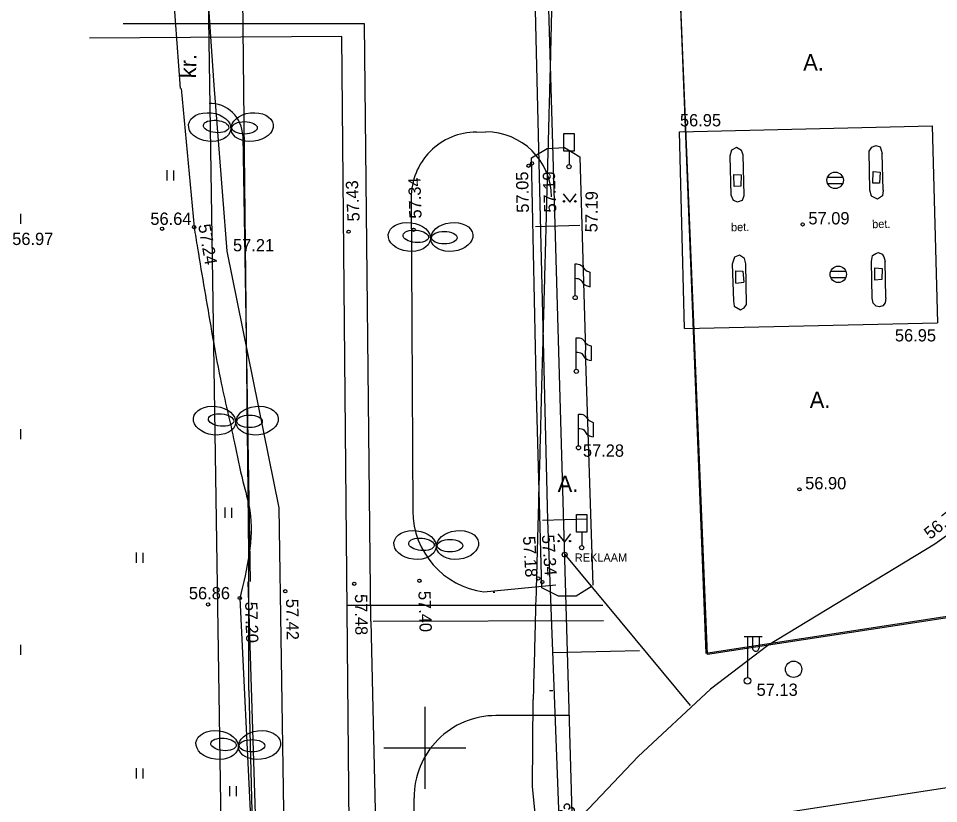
# Model space of a CAD drawing. Extents: x 9156 to 9809, y 2728 to 4000.
# Drawn here: x 9375.2 to 9431.4, y 3596.6 to 3644.5 of the extents above; entities that cross this region are included whole.
import ezdxf

# ---------------------------------------------------------------- set-up
doc = ezdxf.new("R2010")
doc.units = 0
for name, color, linetype in [('Level 11', 7, 'Continuous'), ('Level 12', 7, 'Continuous'), ('Level 14', 7, 'Continuous'), ('Level 15', 7, 'Continuous'), ('Level 16', 7, 'Continuous'), ('Level 18', 7, 'Continuous'), ('Level 54', 7, 'Continuous'), ('Level 56', 7, 'Continuous'), ('Level 7', 7, 'Continuous'), ('Level 8', 7, 'Continuous')]:
    doc.layers.add(name, color=color, linetype=linetype)

msp = doc.modelspace()

# ---------------------------------------------------------------- linework, layer by layer
at = {"layer": 'Level 11'}
for points in [[(9415.081, 3658.579), (9449.014, 3661.975), (9454.803, 3611.437), (9417.243, 3605.687)], [(9454.703, 3611.537), (9449.014, 3661.975), (9415.081, 3658.579), (9417.143, 3605.787)]]:
    msp.add_lwpolyline(points, close=True, dxfattribs=at)
at = {"layer": 'Level 12'}
for p, q in [((9389.26, 3611.821), (9388.899, 3645.893)), ((9389.26, 3603.506), (9389.26, 3611.821)), ((9389.26, 3603.506), (9390.852, 3539.152)), ((9407.609, 3603.506), (9407.816, 3603.506))]:
    msp.add_line(p, q, dxfattribs=at)
at = {"layer": 'Level 14'}
for p, q in [((9396.31, 3644.158), (9381.598, 3644.158)), ((9396.702, 3607.733), (9396.31, 3644.158)), ((9396.702, 3607.733), (9397.759, 3562.139)), ((9396.853, 3607.733), (9410.91, 3607.78))]:
    msp.add_line(p, q, dxfattribs=at)
at = {"layer": 'Level 15'}
msp.add_line((9407.788, 3605.822), (9413.097, 3605.937), dxfattribs=at)
at = {"layer": 'Level 16'}
for p, q in [((9394.939, 3643.387), (9379.538, 3643.283)), ((9395.524, 3581.023), (9394.939, 3643.387)), ((9395.222, 3608.716), (9410.87, 3608.706))]:
    msp.add_line(p, q, dxfattribs=at)
at = {"layer": 'Level 18'}
for p, q in [((9403.149, 3637.566), (9403.715, 3637.569)), ((9388.885, 3637.344), (9389.332, 3610.14)), ((9399.167, 3633.546), (9399.264, 3614.446)), ((9391.373, 3541.836), (9389.227, 3610.137)), ((9403.604, 3609.515), (9407.986, 3609.952)), ((9404.274, 3609.471), (9404.179, 3609.472)), ((9408.82, 3601.971), (9404.342, 3601.971)), ((9399.432, 3578.415), (9399.342, 3596.946))]:
    msp.add_line(p, q, dxfattribs=at)
for centre, radius, start, end in [((9386.885, 3637.312), 2, 0.9413, 91.579), ((9403.167, 3633.566), 4, 90.2544, 180.2913), ((9403.733, 3633.569), 4, 0.6132, 90.2544), ((9404.264, 3614.472), 5, 180.2913, 262.4109), ((9404.342, 3596.971), 5, 90, 180.2781)]:
    msp.add_arc(centre, radius, start, end, dxfattribs=at)
at = {"layer": 'Level 54'}
for p, q in [((9387.136, 3640.425), (9386.589, 3648.491)), ((9384.478, 3648.181), (9385.066, 3640.216)), ((9385.134, 3640.223), (9385.921, 3631.766)), ((9415.544, 3637.576), (9415.544, 3637.576)), ((9430.957, 3637.937), (9430.957, 3637.937)), ((9407.459, 3636.565), (9407.459, 3636.565)), ((9408.531, 3636.632), (9408.531, 3636.632)), ((9418.704, 3636.46), (9418.704, 3636.46)), ((9419.026, 3636.614), (9419.026, 3636.614)), ((9419.328, 3636.436), (9419.328, 3636.436)), ((9427.276, 3636.639), (9427.276, 3636.639)), ((9427.526, 3636.748), (9427.526, 3636.748)), ((9427.783, 3636.657), (9427.783, 3636.657)), ((9406.5, 3635.984), (9406.5, 3635.984)), ((9408.798, 3636.407), (9408.798, 3635.582)), ((9409.457, 3636.062), (9409.457, 3636.062)), ((9418.608, 3636.099), (9418.608, 3636.099)), ((9419.425, 3636.182), (9419.425, 3636.182)), ((9427.117, 3636.399), (9427.117, 3636.399)), ((9427.915, 3636.262), (9427.915, 3636.262)), ((9406.326, 3635.505), (9406.326, 3635.505)), ((9406.54, 3635.649), (9406.54, 3635.649)), ((9408.798, 3635.456), (9408.798, 3635.456)), ((9384.264, 3635.232), (9384.264, 3634.612)), ((9384.669, 3635.22), (9384.669, 3634.612)), ((9418.862, 3634.976), (9418.862, 3634.976)), ((9419.3, 3634.949), (9419.3, 3634.949)), ((9424.58, 3634.821), (9425.496, 3634.821)), ((9427.352, 3635.161), (9427.352, 3635.161)), ((9427.783, 3635.11), (9427.783, 3635.11)), ((9418.867, 3634.236), (9418.867, 3634.236)), ((9419.286, 3634.267), (9419.286, 3634.267)), ((9424.58, 3634.421), (9425.496, 3634.421)), ((9425.038, 3634.621), (9425.038, 3634.621)), ((9427.334, 3634.439), (9427.334, 3634.439)), ((9427.747, 3634.438), (9427.747, 3634.438)), ((9408.436, 3633.787), (9408.839, 3633.282)), ((9408.839, 3633.282), (9409.236, 3633.787)), ((9418.68, 3633.736), (9418.68, 3633.736)), ((9419.479, 3633.686), (9419.479, 3633.686)), ((9427.158, 3634.01), (9427.158, 3634.01)), ((9427.255, 3633.66), (9427.255, 3633.66)), ((9427.927, 3633.673), (9427.927, 3633.673)), ((9427.977, 3634.023), (9427.977, 3634.023)), ((9418.808, 3633.409), (9418.808, 3633.409)), ((9419.083, 3633.311), (9419.083, 3633.311)), ((9419.388, 3633.412), (9419.388, 3633.412)), ((9427.623, 3633.47), (9427.623, 3633.47)), ((9375.322, 3632.584), (9375.322, 3631.975)), ((9423.056, 3631.931), (9423.056, 3631.931)), ((9383.969, 3631.668), (9383.969, 3631.668)), ((9385.921, 3631.766), (9385.921, 3631.766)), ((9395.346, 3631.488), (9395.346, 3631.488)), ((9399.316, 3631.606), (9399.316, 3631.606)), ((9406.75, 3631.786), (9406.75, 3631.786)), ((9409.452, 3631.868), (9409.452, 3631.868)), ((9387.944, 3630.289), (9387.944, 3630.289)), ((9418.891, 3629.932), (9418.891, 3629.932)), ((9419.192, 3630.05), (9419.192, 3630.05)), ((9419.498, 3629.849), (9419.498, 3629.849)), ((9427.322, 3630.029), (9427.322, 3630.029)), ((9427.518, 3630.165), (9427.518, 3630.165)), ((9427.676, 3630.212), (9427.676, 3630.212)), ((9427.901, 3630.126), (9427.901, 3630.126)), ((9428.018, 3629.963), (9428.018, 3629.963)), ((9409.177, 3627.593), (9409.177, 3629.519)), ((9418.763, 3629.51), (9418.763, 3629.51)), ((9419.591, 3629.531), (9419.591, 3629.531)), ((9427.253, 3629.669), (9427.253, 3629.669)), ((9427.464, 3629.281), (9427.464, 3629.281)), ((9427.917, 3629.241), (9427.917, 3629.241)), ((9428.084, 3629.675), (9428.084, 3629.675)), ((9410.078, 3629.015), (9410.078, 3628.125)), ((9418.978, 3629.104), (9418.978, 3629.104)), ((9419.415, 3629.076), (9419.415, 3629.076)), ((9424.772, 3629.086), (9425.688, 3629.086)), ((9424.772, 3628.686), (9425.688, 3628.686)), ((9425.23, 3628.886), (9425.23, 3628.886)), ((9427.895, 3628.563), (9427.895, 3628.563)), ((9418.972, 3628.348), (9418.972, 3628.348)), ((9419.473, 3628.402), (9419.473, 3628.402)), ((9427.46, 3628.539), (9427.46, 3628.539)), ((9409.177, 3627.467), (9409.177, 3627.467)), ((9427.295, 3627.44), (9427.295, 3627.44)), ((9428.123, 3627.448), (9428.123, 3627.448)), ((9418.83, 3627.27), (9418.83, 3627.27)), ((9418.886, 3626.952), (9418.886, 3626.952)), ((9419.632, 3627.037), (9419.632, 3627.037)), ((9427.357, 3627.124), (9427.357, 3627.124)), ((9427.544, 3626.949), (9427.544, 3626.949)), ((9427.748, 3626.912), (9427.748, 3626.912)), ((9427.941, 3626.957), (9427.941, 3626.957)), ((9428.087, 3627.148), (9428.087, 3627.148)), ((9419.253, 3626.727), (9419.253, 3626.727)), ((9419.495, 3626.849), (9419.495, 3626.849)), ((9431.278, 3625.922), (9431.278, 3625.922)), ((9415.855, 3625.589), (9415.855, 3625.589)), ((9409.245, 3623.093), (9409.245, 3625.019)), ((9409.811, 3624.243), (9409.811, 3624.243)), ((9410.146, 3624.515), (9410.146, 3623.625)), ((9409.245, 3622.967), (9409.245, 3622.967)), ((9406.818, 3621.548), (9406.818, 3621.548)), ((9409.376, 3618.432), (9409.376, 3620.358)), ((9410.277, 3619.854), (9410.277, 3618.964)), ((9375.322, 3619.433), (9375.322, 3618.824)), ((9409.376, 3618.306), (9409.376, 3618.306)), ((9422.858, 3615.771), (9422.858, 3615.771)), ((9387.794, 3614.656), (9387.794, 3614.036)), ((9388.199, 3614.645), (9388.199, 3614.036)), ((9391.116, 3614.638), (9391.116, 3614.638)), ((9407.173, 3613.877), (9407.173, 3613.877)), ((9407.476, 3613.881), (9407.476, 3613.881)), ((9409.914, 3613.957), (9409.914, 3613.957)), ((9408.115, 3613.062), (9408.518, 3612.557)), ((9408.518, 3612.557), (9408.915, 3613.062)), ((9409.574, 3613.162), (9409.574, 3612.337)), ((9431.117, 3612.429), (9431.117, 3612.429)), ((9382.392, 3611.913), (9382.392, 3611.293)), ((9382.798, 3611.902), (9382.798, 3611.293)), ((9408.535, 3611.789), (9408.535, 3611.789)), ((9409.574, 3612.211), (9409.574, 3612.211)), ((9399.669, 3610.192), (9399.669, 3610.192)), ((9406.917, 3610.334), (9406.917, 3610.334)), ((9407.171, 3610.117), (9407.171, 3610.117)), ((9391.483, 3609.557), (9391.483, 3609.557)), ((9395.696, 3610.009), (9395.696, 3610.009)), ((9407.132, 3609.759), (9407.132, 3609.759)), ((9410.204, 3609.858), (9410.204, 3609.858)), ((9388.707, 3609.142), (9388.707, 3609.142)), ((9388.707, 3609.142), (9389.518, 3592.556)), ((9408.147, 3609.25), (9408.147, 3609.25)), ((9409.232, 3609.263), (9409.232, 3609.263)), ((9386.777, 3608.752), (9386.777, 3608.752)), ((9419.492, 3606.796), (9420.592, 3606.796)), ((9419.692, 3606.796), (9419.692, 3604.296)), ((9419.992, 3606.796), (9419.992, 3606.096)), ((9420.392, 3606.796), (9420.392, 3606.096)), ((9375.322, 3606.282), (9375.322, 3605.673)), ((9420.928, 3606.248), (9420.928, 3606.248)), ((9419.692, 3604.096), (9419.692, 3604.096)), ((9417.439, 3603.592), (9417.439, 3603.592)), ((9400, 3602.5), (9400, 3597.5)), ((9400, 3602.5), (9400, 3597.5)), ((9400, 3602.5), (9400, 3597.5)), ((9416.186, 3602.596), (9416.186, 3602.596)), ((9397.5, 3600), (9402.5, 3600)), ((9397.5, 3600), (9402.5, 3600)), ((9397.5, 3600), (9402.5, 3600)), ((9413.009, 3599.472), (9413.009, 3599.472)), ((9382.392, 3598.762), (9382.392, 3598.142)), ((9382.798, 3598.75), (9382.798, 3598.142)), ((9388.073, 3597.67), (9388.073, 3597.05)), ((9388.478, 3597.659), (9388.478, 3597.05))]:
    msp.add_line(p, q, dxfattribs=at)
for points in [[(9406.651, 3648.489), (9406.796, 3642.411)], [(9406.796, 3642.411), (9407.476, 3613.881), (9408.676, 3582.388), (9410.387, 3515.117)], [(9438.722, 3642.411), (9439.009, 3638.117), (9439.783, 3627.178), (9439.69, 3625.163), (9439.116, 3623.225), (9438.356, 3621.375), (9436.997, 3618.72), (9435.277, 3616.16), (9432.91, 3613.707), (9431.117, 3612.429), (9420.928, 3606.248), (9417.439, 3603.592), (9413.009, 3599.472), (9408.878, 3595.102), (9406.951, 3592.745)], [(9397.129, 3380.652), (9395.019, 3412.343), (9393.756, 3460.883), (9392.807, 3509.978), (9391.971, 3559.264), (9391.116, 3614.638), (9387.944, 3630.289), (9387.153, 3640.427)], [(9415.855, 3625.589), (9415.544, 3637.576), (9430.957, 3637.937), (9431.278, 3625.922)], [(9410.204, 3609.858), (9409.232, 3609.263), (9408.147, 3609.25), (9407.132, 3609.759), (9406.818, 3621.548), (9406.5, 3635.984), (9407.459, 3636.565), (9408.531, 3636.632), (9409.457, 3636.062), (9409.811, 3624.243)], [(9419.425, 3636.182), (9419.328, 3636.436), (9419.026, 3636.614), (9418.704, 3636.46), (9418.608, 3636.099), (9418.68, 3633.736), (9418.808, 3633.409), (9419.083, 3633.311), (9419.388, 3633.412), (9419.479, 3633.686)], [(9427.977, 3634.023), (9427.927, 3633.673), (9427.623, 3633.47), (9427.255, 3633.66), (9427.158, 3634.01), (9427.117, 3636.399), (9427.276, 3636.639), (9427.526, 3636.748), (9427.783, 3636.657), (9427.915, 3636.262)], [(9419.479, 3633.686), (9419.425, 3636.182)], [(9427.977, 3634.023), (9427.915, 3636.262)], [(9419.286, 3634.267), (9418.867, 3634.236), (9418.862, 3634.976), (9419.3, 3634.949)], [(9419.3, 3634.949), (9419.286, 3634.267)], [(9427.783, 3635.11), (9427.747, 3634.438), (9427.334, 3634.439), (9427.352, 3635.161)], [(9427.352, 3635.161), (9427.783, 3635.11)], [(9409.452, 3631.868), (9406.75, 3631.786)], [(9419.591, 3629.531), (9419.498, 3629.849), (9419.192, 3630.05), (9418.891, 3629.932), (9418.763, 3629.51), (9418.83, 3627.27), (9418.886, 3626.952), (9419.253, 3626.727), (9419.495, 3626.849), (9419.632, 3627.037)], [(9428.123, 3627.448), (9428.087, 3627.148), (9427.941, 3626.957), (9427.748, 3626.912), (9427.544, 3626.949), (9427.357, 3627.124), (9427.295, 3627.44), (9427.253, 3629.669), (9427.322, 3630.029), (9427.518, 3630.165), (9427.676, 3630.212), (9427.901, 3630.126), (9428.018, 3629.963), (9428.084, 3629.675)], [(9419.632, 3627.037), (9419.591, 3629.531)], [(9427.917, 3629.241), (9427.895, 3628.563), (9427.46, 3628.539), (9427.464, 3629.281)], [(9427.464, 3629.281), (9427.917, 3629.241)], [(9428.123, 3627.448), (9428.084, 3629.675)], [(9418.972, 3628.348), (9418.978, 3629.104), (9419.415, 3629.076), (9419.473, 3628.402)], [(9418.972, 3628.348), (9419.473, 3628.402)], [(9415.855, 3625.589), (9431.278, 3625.922)], [(9410.275, 3609.929), (9409.811, 3624.243)], [(9409.914, 3613.957), (9407.173, 3613.877)], [(9408.535, 3611.789), (9416.186, 3602.596)], [(9409.112, 3500.044), (9408.382, 3542.315), (9408.497, 3570.133), (9408.227, 3581.28), (9406.571, 3597.619), (9406.61, 3602.955)]]:
    msp.add_lwpolyline(points, dxfattribs=at)
for points in [[(9408.481, 3637.483), (9409.115, 3637.483), (9409.115, 3636.407), (9408.481, 3636.407)], [(9409.257, 3614.238), (9409.891, 3614.238), (9409.891, 3613.162), (9409.257, 3613.162)]]:
    msp.add_lwpolyline(points, close=True, dxfattribs=at)
for centre, radius in [((9406.326, 3635.505), 0.1), ((9406.54, 3635.649), 0.1), ((9408.798, 3635.456), 0.126), ((9425.038, 3634.621), 0.5), ((9408.486, 3633.337), 0.0428), ((9409.186, 3633.337), 0.0452), ((9423.056, 3631.931), 0.1), ((9383.969, 3631.668), 0.1), ((9385.921, 3631.766), 0.1), ((9395.346, 3631.488), 0.1), ((9399.316, 3631.606), 0.1), ((9425.23, 3628.886), 0.5), ((9409.177, 3627.467), 0.126), ((9409.245, 3622.967), 0.126), ((9409.376, 3618.306), 0.126), ((9422.858, 3615.771), 0.1), ((9408.165, 3612.612), 0.0428), ((9408.865, 3612.612), 0.0452), ((9409.574, 3612.211), 0.126), ((9408.535, 3611.789), 0.148), ((9395.696, 3610.009), 0.1), ((9399.669, 3610.192), 0.1), ((9406.917, 3610.334), 0.1), ((9407.171, 3610.117), 0.1), ((9391.483, 3609.557), 0.1), ((9388.707, 3609.142), 0.1), ((9386.777, 3608.752), 0.1), ((9422.503, 3604.794), 0.5), ((9419.692, 3604.096), 0.2)]:
    msp.add_circle(centre, radius, dxfattribs=at)
msp.add_arc((9420.192, 3606.096), 0.2, 179.9393, 0.0607, dxfattribs=at)
for points, degree in [([(9436.731, 3685.954), (9412.763, 3679.921), (9412.256, 3679.783), (9412.019, 3679.731), (9411.816, 3679.574), (9411.512, 3678.968), (9408.609, 3671.162), (9408.49, 3670.833), (9408.444, 3670.642), (9408.427, 3670.482), (9407.671, 3642.411)], 3), ([(9407.671, 3642.411), (9407.414, 3632.864), (9407.07, 3620.079), (9406.61, 3602.955)], 2)]:
    msp.add_open_spline(points, degree=degree, dxfattribs=at)
for points in [[(9385.921, 3631.766), (9386.128, 3630.481), (9386.99, 3625.4), (9387.525, 3622.489), (9388.384, 3618.613), (9388.897, 3616.251), (9389.316, 3614.486), (9388.707, 3609.142)], [(9409.177, 3629.519), (9409.527, 3629.454), (9409.759, 3629.188), (9410.078, 3629.015)], [(9409.177, 3628.644), (9409.504, 3628.555), (9409.671, 3628.322), (9410.079, 3628.126)], [(9409.245, 3625.019), (9409.595, 3624.954), (9409.827, 3624.688), (9410.146, 3624.515)], [(9409.245, 3624.144), (9409.572, 3624.055), (9409.739, 3623.822), (9410.147, 3623.626)], [(9409.376, 3620.358), (9409.726, 3620.293), (9409.958, 3620.027), (9410.277, 3619.854)], [(9409.376, 3619.483), (9409.703, 3619.394), (9409.87, 3619.161), (9410.278, 3618.965)]]:
    msp.add_spline(points, degree=3, dxfattribs=at)
at = {"layer": 'Level 56'}
for p, q in [((9403.149, 3637.566), (9403.715, 3637.569)), ((9388.885, 3637.344), (9389.332, 3610.14)), ((9399.167, 3633.546), (9399.264, 3614.446)), ((9391.373, 3541.836), (9389.227, 3610.137)), ((9403.604, 3609.515), (9407.986, 3609.952)), ((9404.274, 3609.471), (9404.179, 3609.472)), ((9408.82, 3601.971), (9404.342, 3601.971)), ((9399.432, 3578.415), (9399.342, 3596.946))]:
    msp.add_line(p, q, dxfattribs=at)
for centre, radius, start, end in [((9386.885, 3637.312), 2, 0.9413, 91.579), ((9403.167, 3633.566), 4, 90.2544, 180.2913), ((9403.733, 3633.569), 4, 0.6132, 90.2544), ((9404.264, 3614.472), 5, 180.2913, 262.4109), ((9404.342, 3596.971), 5, 90, 180.2781)]:
    msp.add_arc(centre, radius, start, end, dxfattribs=at)
at = {"layer": 'Level 7'}
for p, q in [((9387.795, 3580.728), (9386.2, 3684.47)), ((9407.89, 3634.03), (9406.73, 3674)), ((9409.05, 3594.06), (9407.89, 3634.03)), ((9435.465, 3598.13), (9409.05, 3594.06))]:
    msp.add_line(p, q, dxfattribs=at)
at = {"layer": 'Level 8'}
for centre, major_axis, ratio in [((9386.868, 3637.867), (1.285, -0.15), 0.674652), ((9386.868, 3637.867), (1.285, -0.15), 0.674652), ((9386.868, 3637.867), (1.285, -0.15), 0.674652), ((9386.868, 3637.867), (1.285, -0.15), 0.674652), ((9389.46, 3637.867), (-1.285, -0.15), 0.674652), ((9389.46, 3637.867), (-1.285, -0.15), 0.674652), ((9389.46, 3637.867), (-1.285, -0.15), 0.674652), ((9389.46, 3637.867), (-1.285, -0.15), 0.674652), ((9387.263, 3637.904), (0.774, -0.072), 0.486914), ((9387.263, 3637.904), (0.774, -0.072), 0.486914), ((9387.263, 3637.904), (0.774, -0.072), 0.486914), ((9387.263, 3637.904), (0.774, -0.072), 0.486914), ((9389, 3637.824), (-0.778, 0.002), 0.486914), ((9389, 3637.824), (-0.778, 0.002), 0.486914), ((9389, 3637.824), (-0.778, 0.002), 0.486914), ((9389, 3637.824), (-0.778, 0.002), 0.486914), ((9399.054, 3631.165), (1.285, -0.15), 0.674652), ((9399.054, 3631.165), (1.285, -0.15), 0.674652), ((9399.054, 3631.165), (1.285, -0.15), 0.674652), ((9399.054, 3631.165), (1.285, -0.15), 0.674652), ((9401.646, 3631.165), (-1.285, -0.15), 0.674652), ((9401.646, 3631.165), (-1.285, -0.15), 0.674652), ((9401.646, 3631.165), (-1.285, -0.15), 0.674652), ((9401.646, 3631.165), (-1.285, -0.15), 0.674652), ((9399.449, 3631.202), (0.774, -0.072), 0.486914), ((9399.449, 3631.202), (0.774, -0.072), 0.486914), ((9399.449, 3631.202), (0.774, -0.072), 0.486914), ((9399.449, 3631.202), (0.774, -0.072), 0.486914), ((9401.186, 3631.122), (-0.778, 0.002), 0.486914), ((9401.186, 3631.122), (-0.778, 0.002), 0.486914), ((9401.186, 3631.122), (-0.778, 0.002), 0.486914), ((9401.186, 3631.122), (-0.778, 0.002), 0.486914), ((9387.17, 3619.965), (1.285, -0.15), 0.674652), ((9387.17, 3619.965), (1.285, -0.15), 0.674652), ((9387.17, 3619.965), (1.285, -0.15), 0.674652), ((9387.17, 3619.965), (1.285, -0.15), 0.674652), ((9389.762, 3619.965), (-1.285, -0.15), 0.674652), ((9389.762, 3619.965), (-1.285, -0.15), 0.674652), ((9389.762, 3619.965), (-1.285, -0.15), 0.674652), ((9389.762, 3619.965), (-1.285, -0.15), 0.674652), ((9387.565, 3620.001), (0.774, -0.072), 0.486914), ((9387.565, 3620.001), (0.774, -0.072), 0.486914), ((9387.565, 3620.001), (0.774, -0.072), 0.486914), ((9387.565, 3620.001), (0.774, -0.072), 0.486914), ((9389.302, 3619.921), (-0.778, 0.002), 0.486914), ((9389.302, 3619.921), (-0.778, 0.002), 0.486914), ((9389.302, 3619.921), (-0.778, 0.002), 0.486914), ((9389.302, 3619.921), (-0.778, 0.002), 0.486914), ((9399.402, 3612.378), (1.285, -0.15), 0.674652), ((9399.402, 3612.378), (1.285, -0.15), 0.674652), ((9399.402, 3612.378), (1.285, -0.15), 0.674652), ((9399.402, 3612.378), (1.285, -0.15), 0.674652), ((9401.995, 3612.378), (-1.285, -0.15), 0.674652), ((9401.995, 3612.378), (-1.285, -0.15), 0.674652), ((9401.995, 3612.378), (-1.285, -0.15), 0.674652), ((9401.995, 3612.378), (-1.285, -0.15), 0.674652), ((9399.797, 3612.414), (0.774, -0.072), 0.486914), ((9399.797, 3612.414), (0.774, -0.072), 0.486914), ((9399.797, 3612.414), (0.774, -0.072), 0.486914), ((9399.797, 3612.414), (0.774, -0.072), 0.486914), ((9401.535, 3612.334), (-0.778, 0.002), 0.486914), ((9401.535, 3612.334), (-0.778, 0.002), 0.486914), ((9401.535, 3612.334), (-0.778, 0.002), 0.486914), ((9401.535, 3612.334), (-0.778, 0.002), 0.486914), ((9387.321, 3600.174), (1.285, -0.15), 0.674652), ((9387.321, 3600.174), (1.285, -0.15), 0.674652), ((9387.321, 3600.174), (1.285, -0.15), 0.674652), ((9387.321, 3600.174), (1.285, -0.15), 0.674652), ((9389.913, 3600.174), (-1.285, -0.15), 0.674652), ((9389.913, 3600.174), (-1.285, -0.15), 0.674652), ((9389.913, 3600.174), (-1.285, -0.15), 0.674652), ((9389.913, 3600.174), (-1.285, -0.15), 0.674652), ((9387.716, 3600.21), (0.774, -0.072), 0.486914), ((9387.716, 3600.21), (0.774, -0.072), 0.486914), ((9387.716, 3600.21), (0.774, -0.072), 0.486914), ((9387.716, 3600.21), (0.774, -0.072), 0.486914), ((9389.453, 3600.13), (-0.778, 0.002), 0.486914), ((9389.453, 3600.13), (-0.778, 0.002), 0.486914), ((9389.453, 3600.13), (-0.778, 0.002), 0.486914), ((9389.453, 3600.13), (-0.778, 0.002), 0.486914)]:
    msp.add_ellipse(centre, major_axis=major_axis, ratio=ratio, dxfattribs=at)

# ---------------------------------------------------------------- texts
at = {"layer": 'Level 54'}
for s, height, rotation, p in [('kr.', 1, 88.3866, (9386.029, 3640.835)), ('57.34', 0.75, 91.644, (9399.803, 3632.296)), ('57.05', 0.75, 91.2423, (9406.356, 3632.653)), ('57.19', 0.75, 92.1661, (9408.03, 3632.669)), ('57.43', 0.75, 92.5394, (9396.028, 3632.125)), ('57.19', 0.75, 89.4117, (9410.532, 3631.446)), ('57.24', 0.75, 279.972, (9386.165, 3631.886)), ('bet.', 0.5, 1.2914, (9418.689, 3631.508)), ('bet.', 0.5, 1.2914, (9427.302, 3631.698)), ('56.79', 0.75, 38.7166, (9430.841, 3612.682)), ('57.18', 0.75, 273.6206, (9405.984, 3612.893)), ('57.34', 0.75, 274.0616, (9407.139, 3612.982)), ('57.40', 0.75, 271.8176, (9399.603, 3609.565)), ('57.42', 0.75, 270.8222, (9391.531, 3609.089)), ('57.48', 0.75, 270.6818, (9395.732, 3609.381)), ('57.20', 0.75, 271.5527, (9389.031, 3608.902)), ('57.33', 0.75, 48.559, (9407.615, 3594.37))]:
    msp.add_text(s, height=height, rotation=rotation, dxfattribs=at).set_placement(p)
for s, height, p in [('A.', 1, (9423.089, 3641.316)), ('56.95', 0.75, (9415.567, 3637.911)), ('56.64', 0.75, (9383.251, 3631.903)), ('57.09', 0.75, (9423.406, 3631.931)), ('56.97', 0.75, (9374.82, 3630.674)), ('57.21', 0.75, (9388.294, 3630.289)), ('56.95', 0.75, (9428.685, 3624.791)), ('A.', 1, (9423.488, 3620.733)), ('57.28', 0.75, (9409.644, 3617.761)), ('A.', 1, (9408.105, 3615.61)), ('56.90', 0.75, (9423.208, 3615.771)), ('REKLAAM', 0.5, (9409.151, 3611.358)), ('56.86', 0.75, (9385.601, 3609.065)), ('57.13', 0.75, (9420.246, 3603.174))]:
    msp.add_text(s, height=height, dxfattribs=at).set_placement(p)

doc.saveas('drawing.dxf')
